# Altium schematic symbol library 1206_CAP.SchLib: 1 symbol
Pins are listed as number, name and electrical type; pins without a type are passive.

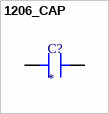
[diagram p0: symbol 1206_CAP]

## 1206_CAP
designator C?
1206 CAP
footprint 1206
pins: 1, 2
